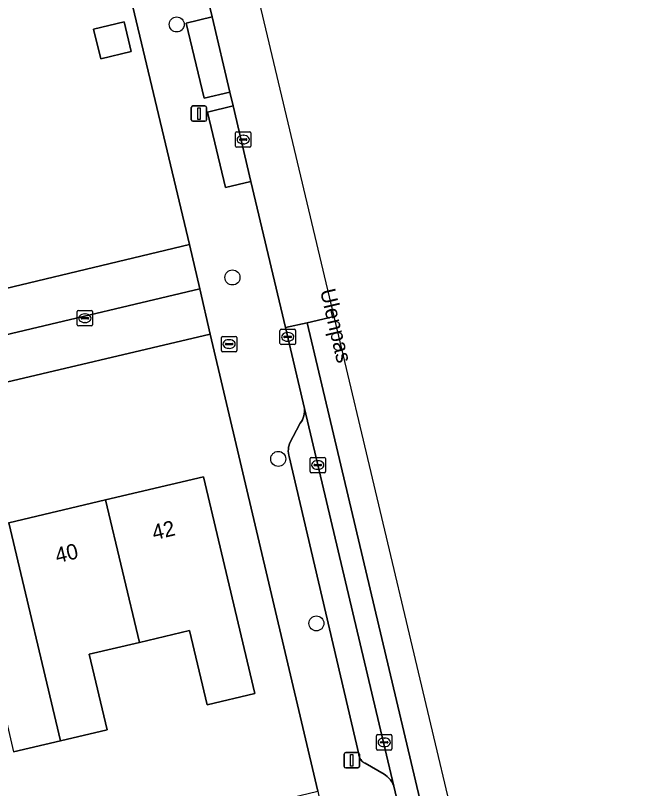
# Model space of a CAD drawing. Extents: x 157648 to 158502, y 379212 to 380938.
# Drawn here: x 158351.9 to 158392.5, y 380782.3 to 380832.6 of the extents above; entities that cross this region are included whole.
import ezdxf

# ---------------------------------------------------------------- set-up
doc = ezdxf.new("R2010")
doc.units = 0
for name, color, linetype in [('IMGEO_Boom', 7, 'Continuous'), ('IMGEO_Brandkraan', 7, 'Continuous'), ('IMGEO_Erf', 7, 'Continuous'), ('IMGEO_Groenvoorziening', 7, 'Continuous'), ('IMGEO_Kolk', 7, 'Continuous'), ('IMGEO_Lichtmast', 7, 'Continuous'), ('IMGEO_Openbare_ruimte_label', 7, 'Continuous'), ('IMGEO_Pand', 7, 'Continuous'), ('IMGEO_Pand_nummerreeks', 7, 'Continuous'), ('IMGEO_Parkeervlak_open', 7, 'Continuous'), ('IMGEO_Rijbaan_lokaal_gesloten', 7, 'Continuous'), ('IMGEO_Rijbaan_lokaal_open', 7, 'Continuous'), ('IMGEO_Voetpad_open', 7, 'Continuous')]:
    doc.layers.add(name, color=color, linetype=linetype)

msp = doc.modelspace()

# ---------------------------------------------------------------- linework, layer by layer
at = {"layer": 'IMGEO_Boom'}
for centre in [(158362.389, 380831.984), (158366.013, 380815.521), (158368.991, 380803.717), (158371.472, 380793.018)]:
    msp.add_circle(centre, 0.489, dxfattribs=at)
at = {"layer": 'IMGEO_Brandkraan'}
for p, q in [((158365.293, 380810.765), (158365.293, 380811.617)), ((158365.368, 380811.691), (158366.22, 380811.691)), ((158365.781, 380811.471), (158365.806, 380811.471)), ((158366.294, 380811.617), (158366.294, 380810.765)), ((158365.552, 380811.185), (158365.552, 380811.197)), ((158365.99, 380811.148), (158365.592, 380811.148)), ((158365.595, 380811.234), (158365.993, 380811.234)), ((158365.804, 380810.911), (158365.779, 380810.911)), ((158366.036, 380811.197), (158366.036, 380811.185)), ((158366.22, 380810.691), (158365.368, 380810.691))]:
    msp.add_line(p, q, dxfattribs=at)
for points in [[(158365.293, 380810.765), (158365.293, 380811.617)], [(158365.368, 380811.691), (158366.22, 380811.691)], [(158366.294, 380811.617), (158366.294, 380810.765)], [(158366.22, 380810.691), (158365.368, 380810.691)]]:
    msp.add_lwpolyline(points, dxfattribs=at)
for centre, radius, start, end in [((158365.37, 380811.615), 0.0765, 91.552, 178.448), ((158365.37, 380811.615), 0.0765, 91.552, 178.448), ((158366.218, 380811.615), 0.0765, 1.552, 88.448), ((158366.218, 380811.615), 0.0765, 1.552, 88.448), ((158365.37, 380810.767), 0.0765, 181.552, 268.448), ((158365.37, 380810.767), 0.0765, 181.552, 268.448), ((158365.592, 380811.194), 0.0403, 85.8775, 175.7526), ((158365.589, 380811.184), 0.0366, 178.938, 274.7102), ((158365.993, 380811.191), 0.043, 264.8664, 352.4533), ((158365.997, 380811.196), 0.0386, 1.7309, 96.639), ((158366.218, 380810.767), 0.0765, 271.552, 358.448), ((158366.218, 380810.767), 0.0765, 271.552, 358.448)]:
    msp.add_arc(centre, radius, start, end, dxfattribs=at)
for centre, major_axis, ratio, start_param, end_param in [((158365.78, 380811.191), (-0.387, 0.002), 0.722429, 4.712389, 7.853982), ((158365.805, 380811.191), (-0.39, 0.002), 0.717154, 1.570796, 4.712389)]:
    msp.add_ellipse(centre, major_axis=major_axis, ratio=ratio, start_param=start_param, end_param=end_param, dxfattribs=at)
at = {"layer": 'IMGEO_Erf'}
for points in [[(158346.135, 380837.142), (158347.662, 380830.717), (158348.081, 380828.951), (158350.047, 380829.418), (158351.124, 380824.885), (158349.158, 380824.417), (158350.661, 380818.095), (158345.233, 380816.805), (158344.065, 380816.528), (158343.54, 380816.403), (158344.245, 380813.436), (158344.77, 380813.561), (158345.938, 380813.838), (158346.006, 380813.552), (158363.215, 380817.667), (158352.177, 380864.073)], [(158344.495, 380775.601), (158371.565, 380782.109), (158364.564, 380811.841), (158335.11, 380804.894)], [(158351.466, 380799.554), (158357.767, 380801.046), (158364.124, 380802.552), (158367.46, 380788.461), (158364.364, 380787.728), (158363.221, 380792.554), (158359.96, 380791.782), (158356.699, 380791.01), (158357.865, 380786.089), (158354.825, 380785.369), (158351.786, 380784.65)]]:
    msp.add_lwpolyline(points, dxfattribs=at)
msp.add_lwpolyline([(158358.978, 380832.144), (158359.435, 380830.221), (158357.446, 380829.748), (158356.989, 380831.671)], close=True, dxfattribs=at)
at = {"layer": 'IMGEO_Groenvoorziening'}
msp.add_lwpolyline([(158363.902, 380814.78), (158363.215, 380817.667), (158346.006, 380813.552), (158338.72, 380811.781), (158339.383, 380808.977)], close=True, dxfattribs=at)
at = {"layer": 'IMGEO_Kolk'}
for p, q in [((158366.214, 380824.069), (158366.214, 380824.921)), ((158366.289, 380824.995), (158367.141, 380824.995)), ((158367.215, 380824.921), (158367.215, 380824.069)), ((158366.473, 380824.489), (158366.473, 380824.501)), ((158366.911, 380824.452), (158366.513, 380824.452)), ((158366.516, 380824.538), (158366.914, 380824.538)), ((158366.702, 380824.775), (158366.727, 380824.775)), ((158366.957, 380824.501), (158366.957, 380824.489)), ((158367.141, 380823.995), (158366.289, 380823.995)), ((158366.725, 380824.215), (158366.7, 380824.215)), ((158355.922, 380812.445), (158355.922, 380813.297)), ((158355.997, 380813.371), (158356.849, 380813.371)), ((158356.923, 380813.297), (158356.923, 380812.445)), ((158356.181, 380812.865), (158356.181, 380812.877)), ((158356.619, 380812.828), (158356.221, 380812.828)), ((158356.224, 380812.914), (158356.622, 380812.914)), ((158356.41, 380813.151), (158356.435, 380813.151)), ((158356.665, 380812.877), (158356.665, 380812.865)), ((158356.849, 380812.371), (158355.997, 380812.371)), ((158356.433, 380812.591), (158356.408, 380812.591)), ((158369.105, 380811.228), (158369.105, 380812.08)), ((158369.18, 380812.154), (158370.032, 380812.154)), ((158369.593, 380811.934), (158369.618, 380811.934)), ((158370.106, 380812.08), (158370.106, 380811.228)), ((158369.364, 380811.648), (158369.364, 380811.66)), ((158369.802, 380811.611), (158369.404, 380811.611)), ((158369.407, 380811.697), (158369.805, 380811.697)), ((158369.616, 380811.374), (158369.591, 380811.374)), ((158369.848, 380811.66), (158369.848, 380811.648)), ((158370.032, 380811.154), (158369.18, 380811.154)), ((158371.059, 380802.893), (158371.059, 380803.745)), ((158371.134, 380803.819), (158371.986, 380803.819)), ((158372.06, 380803.745), (158372.06, 380802.893)), ((158371.318, 380803.313), (158371.318, 380803.325)), ((158371.756, 380803.276), (158371.358, 380803.276)), ((158371.361, 380803.362), (158371.759, 380803.362)), ((158371.547, 380803.599), (158371.572, 380803.599)), ((158371.802, 380803.325), (158371.802, 380803.313)), ((158371.986, 380802.819), (158371.134, 380802.819)), ((158371.57, 380803.039), (158371.545, 380803.039)), ((158375.384, 380784.852), (158375.384, 380785.704)), ((158375.459, 380785.778), (158376.311, 380785.778)), ((158376.385, 380785.704), (158376.385, 380784.852)), ((158375.643, 380785.272), (158375.643, 380785.284)), ((158376.081, 380785.235), (158375.683, 380785.235)), ((158375.686, 380785.321), (158376.084, 380785.321)), ((158375.872, 380785.558), (158375.897, 380785.558)), ((158376.127, 380785.284), (158376.127, 380785.272)), ((158376.311, 380784.778), (158375.459, 380784.778)), ((158375.895, 380784.998), (158375.87, 380784.998))]:
    msp.add_line(p, q, dxfattribs=at)
for points in [[(158366.214, 380824.069), (158366.214, 380824.921)], [(158366.289, 380824.995), (158367.141, 380824.995)], [(158367.215, 380824.921), (158367.215, 380824.069)], [(158367.141, 380823.995), (158366.289, 380823.995)], [(158355.922, 380812.445), (158355.922, 380813.297)], [(158355.997, 380813.371), (158356.849, 380813.371)], [(158356.923, 380813.297), (158356.923, 380812.445)], [(158356.849, 380812.371), (158355.997, 380812.371)], [(158369.105, 380811.228), (158369.105, 380812.08)], [(158369.18, 380812.154), (158370.032, 380812.154)], [(158370.106, 380812.08), (158370.106, 380811.228)], [(158370.032, 380811.154), (158369.18, 380811.154)], [(158371.059, 380802.893), (158371.059, 380803.745)], [(158371.134, 380803.819), (158371.986, 380803.819)], [(158372.06, 380803.745), (158372.06, 380802.893)], [(158371.986, 380802.819), (158371.134, 380802.819)], [(158375.384, 380784.852), (158375.384, 380785.704)], [(158375.459, 380785.778), (158376.311, 380785.778)], [(158376.385, 380785.704), (158376.385, 380784.852)], [(158376.311, 380784.778), (158375.459, 380784.778)]]:
    msp.add_lwpolyline(points, dxfattribs=at)
for centre, radius, start, end in [((158366.291, 380824.919), 0.0765, 91.552, 178.448), ((158366.291, 380824.919), 0.0765, 91.552, 178.448), ((158367.139, 380824.919), 0.0765, 1.552, 88.448), ((158367.139, 380824.919), 0.0765, 1.552, 88.448), ((158366.513, 380824.498), 0.0403, 85.8775, 175.7526), ((158366.51, 380824.488), 0.0366, 178.938, 274.7102), ((158366.914, 380824.495), 0.043, 264.8664, 352.4533), ((158366.918, 380824.5), 0.0386, 1.7309, 96.639), ((158366.291, 380824.071), 0.0765, 181.552, 268.448), ((158366.291, 380824.071), 0.0765, 181.552, 268.448), ((158367.139, 380824.071), 0.0765, 271.552, 358.448), ((158367.139, 380824.071), 0.0765, 271.552, 358.448), ((158355.999, 380813.295), 0.0765, 91.552, 178.448), ((158355.999, 380813.295), 0.0765, 91.552, 178.448), ((158356.847, 380813.295), 0.0765, 1.552, 88.448), ((158356.847, 380813.295), 0.0765, 1.552, 88.448), ((158356.221, 380812.874), 0.0403, 85.8775, 175.7526), ((158356.218, 380812.864), 0.0366, 178.938, 274.7102), ((158356.622, 380812.871), 0.043, 264.8664, 352.4533), ((158356.626, 380812.876), 0.0386, 1.7309, 96.639), ((158355.999, 380812.447), 0.0765, 181.552, 268.448), ((158355.999, 380812.447), 0.0765, 181.552, 268.448), ((158356.847, 380812.447), 0.0765, 271.552, 358.448), ((158356.847, 380812.447), 0.0765, 271.552, 358.448), ((158369.182, 380812.078), 0.0765, 91.552, 178.448), ((158369.182, 380812.078), 0.0765, 91.552, 178.448), ((158370.03, 380812.078), 0.0765, 1.552, 88.448), ((158370.03, 380812.078), 0.0765, 1.552, 88.448), ((158369.404, 380811.657), 0.0403, 85.8775, 175.7526), ((158369.401, 380811.647), 0.0366, 178.938, 274.7102), ((158369.805, 380811.654), 0.043, 264.8664, 352.4533), ((158369.809, 380811.659), 0.0386, 1.7309, 96.639), ((158369.182, 380811.23), 0.0765, 181.552, 268.448), ((158369.182, 380811.23), 0.0765, 181.552, 268.448), ((158370.03, 380811.23), 0.0765, 271.552, 358.448), ((158370.03, 380811.23), 0.0765, 271.552, 358.448), ((158371.136, 380803.743), 0.0765, 91.552, 178.448), ((158371.136, 380803.743), 0.0765, 91.552, 178.448), ((158371.984, 380803.743), 0.0765, 1.552, 88.448), ((158371.984, 380803.743), 0.0765, 1.552, 88.448), ((158371.358, 380803.322), 0.0403, 85.8775, 175.7526), ((158371.355, 380803.312), 0.0366, 178.938, 274.7102), ((158371.759, 380803.319), 0.043, 264.8664, 352.4533), ((158371.763, 380803.324), 0.0386, 1.7309, 96.639), ((158371.136, 380802.895), 0.0765, 181.552, 268.448), ((158371.136, 380802.895), 0.0765, 181.552, 268.448), ((158371.984, 380802.895), 0.0765, 271.552, 358.448), ((158371.984, 380802.895), 0.0765, 271.552, 358.448), ((158375.461, 380785.702), 0.0765, 91.552, 178.448), ((158375.461, 380785.702), 0.0765, 91.552, 178.448), ((158376.309, 380785.702), 0.0765, 1.552, 88.448), ((158376.309, 380785.702), 0.0765, 1.552, 88.448), ((158375.683, 380785.281), 0.0403, 85.8775, 175.7526), ((158375.68, 380785.271), 0.0366, 178.938, 274.7102), ((158376.084, 380785.278), 0.043, 264.8664, 352.4533), ((158376.088, 380785.283), 0.0386, 1.7309, 96.639), ((158375.461, 380784.854), 0.0765, 181.552, 268.448), ((158375.461, 380784.854), 0.0765, 181.552, 268.448), ((158376.309, 380784.854), 0.0765, 271.552, 358.448), ((158376.309, 380784.854), 0.0765, 271.552, 358.448)]:
    msp.add_arc(centre, radius, start, end, dxfattribs=at)
for centre, major_axis, ratio, start_param, end_param in [((158366.701, 380824.495), (-0.387, 0.002), 0.722429, 4.712389, 7.853982), ((158366.726, 380824.495), (-0.39, 0.002), 0.717154, 1.570796, 4.712389), ((158356.409, 380812.871), (-0.387, 0.002), 0.722429, 4.712389, 7.853982), ((158356.434, 380812.871), (-0.39, 0.002), 0.717154, 1.570796, 4.712389), ((158369.592, 380811.654), (-0.387, 0.002), 0.722429, 4.712389, 7.853982), ((158369.617, 380811.654), (-0.39, 0.002), 0.717154, 1.570796, 4.712389), ((158371.546, 380803.319), (-0.387, 0.002), 0.722429, 4.712389, 7.853982), ((158371.571, 380803.319), (-0.39, 0.002), 0.717154, 1.570796, 4.712389), ((158375.871, 380785.278), (-0.387, 0.002), 0.722429, 4.712389, 7.853982), ((158375.896, 380785.278), (-0.39, 0.002), 0.717154, 1.570796, 4.712389)]:
    msp.add_ellipse(centre, major_axis=major_axis, ratio=ratio, start_param=start_param, end_param=end_param, dxfattribs=at)
at = {"layer": 'IMGEO_Lichtmast'}
for p, q in [((158363.336, 380825.783), (158363.336, 380826.583)), ((158363.336, 380826.583), (158363.336, 380825.783)), ((158363.436, 380826.683), (158364.226, 380826.683)), ((158364.226, 380826.683), (158363.436, 380826.683)), ((158364.326, 380826.583), (158364.326, 380825.783)), ((158364.326, 380825.783), (158364.326, 380826.583)), ((158364.226, 380825.683), (158363.436, 380825.683)), ((158363.436, 380825.683), (158364.226, 380825.683)), ((158373.38, 380784.611), (158374.17, 380784.611)), ((158374.17, 380784.611), (158373.38, 380784.611)), ((158373.28, 380783.711), (158373.28, 380784.511)), ((158373.28, 380784.511), (158373.28, 380783.711)), ((158374.27, 380784.511), (158374.27, 380783.711)), ((158374.27, 380783.711), (158374.27, 380784.511)), ((158374.17, 380783.611), (158373.38, 380783.611)), ((158373.38, 380783.611), (158374.17, 380783.611))]:
    msp.add_line(p, q, dxfattribs=at)
for points in [[(158363.756, 380826.558), (158363.906, 380826.558), (158363.906, 380825.808), (158363.756, 380825.808), (158363.756, 380826.558)], [(158373.7, 380784.486), (158373.85, 380784.486), (158373.85, 380783.736), (158373.7, 380783.736), (158373.7, 380784.486)]]:
    msp.add_lwpolyline(points, dxfattribs=at)
for centre, start, end in [((158363.436, 380826.583), 90, 180), ((158363.436, 380826.583), 90, 180), ((158364.226, 380826.583), 0, 90), ((158364.226, 380826.583), 360, 90), ((158363.436, 380825.783), 180, 270), ((158363.436, 380825.783), 180, 270), ((158364.226, 380825.783), 270, 0), ((158364.226, 380825.783), 270, 0), ((158373.38, 380784.511), 90, 180), ((158373.38, 380784.511), 90, 180), ((158374.17, 380784.511), 0, 90), ((158374.17, 380784.511), 360, 90), ((158373.38, 380783.711), 180, 270), ((158373.38, 380783.711), 180, 270), ((158374.17, 380783.711), 270, 0), ((158374.17, 380783.711), 270, 0)]:
    msp.add_arc(centre, 0.1, start, end, dxfattribs=at)
at = {"layer": 'IMGEO_Pand'}
for points in [[(158359.435, 380830.221), (158358.978, 380832.144), (158356.989, 380831.671), (158357.446, 380829.748)], [(158357.767, 380801.046), (158359.96, 380791.782), (158363.221, 380792.554), (158364.364, 380787.728), (158367.46, 380788.461), (158364.124, 380802.552)], [(158357.767, 380801.046), (158351.466, 380799.554), (158354.825, 380785.369), (158357.865, 380786.089), (158356.699, 380791.01), (158359.96, 380791.782)], [(158345.168, 380798.063), (158347.37, 380788.764), (158350.629, 380789.535), (158351.786, 380784.65), (158354.825, 380785.369), (158351.466, 380799.554)]]:
    msp.add_lwpolyline(points, close=True, dxfattribs=at)
at = {"layer": 'IMGEO_Parkeervlak_open'}
for points in [[(158364.691, 380832.473), (158363.007, 380832.077), (158364.183, 380827.181), (158365.847, 380827.574)], [(158367.219, 380821.763), (158366.055, 380826.693), (158364.381, 380826.278), (158365.559, 380821.376)], [(158376.507, 380782.435), (158370.69, 380806.999), (158370.694, 380806.912), (158370.69, 380806.78), (158370.674, 380806.648), (158370.647, 380806.519), (158370.608, 380806.392), (158370.558, 380806.269), (158370.497, 380806.152), (158370.426, 380806.04), (158369.728, 380804.726), (158369.691, 380804.601), (158369.665, 380804.474), (158369.65, 380804.344), (158369.647, 380804.214), (158369.656, 380804.084), (158369.676, 380803.956), (158369.695, 380803.876), (158374.231, 380784.5), (158374.238, 380784.438), (158374.251, 380784.377), (158374.27, 380784.317), (158374.293, 380784.259), (158374.322, 380784.204), (158374.356, 380784.151), (158374.394, 380784.101), (158374.436, 380784.055), (158374.482, 380784.014), (158374.532, 380783.976), (158374.585, 380783.943), (158374.645, 380783.913), (158375.882, 380783.203), (158375.961, 380783.147), (158376.077, 380783.05), (158376.185, 380782.944), (158376.282, 380782.828), (158376.369, 380782.704), (158376.444, 380782.573)]]:
    msp.add_lwpolyline(points, close=True, dxfattribs=at)
at = {"layer": 'IMGEO_Rijbaan_lokaal_gesloten'}
for points in [[(158372.618, 380812.974), (158372.618, 380812.974), (158370.865, 380812.579), (158379.338, 380776.722)], [(158381.005, 380777.591), (158372.618, 380812.974)]]:
    msp.add_lwpolyline(points, dxfattribs=at)
msp.add_lwpolyline([(158392.483, 380720.813), (158380.048, 380773.723), (158379.338, 380776.722), (158370.865, 380812.579), (158369.462, 380812.262), (158370.69, 380806.999), (158376.507, 380782.435), (158376.683, 380781.692), (158377.548, 380778.041), (158378.958, 380772.087), (158379.023, 380771.812), (158384.193, 380750), (158391.081, 380720.484)], close=True, dxfattribs=at)
at = {"layer": 'IMGEO_Rijbaan_lokaal_open'}
msp.add_lwpolyline([(158366.942, 380836.924), (158365.174, 380836.518), (158363.81, 380836.205), (158364.691, 380832.473), (158365.847, 380827.574), (158366.055, 380826.693), (158367.219, 380821.763), (158369.462, 380812.262), (158370.865, 380812.579), (158372.618, 380812.974), (158372.618, 380812.974), (158366.942, 380836.924)], dxfattribs=at)
at = {"layer": 'IMGEO_Voetpad_open'}
for points in [[(158352.177, 380864.073), (158363.215, 380817.667), (158363.902, 380814.78), (158364.564, 380811.841), (158371.565, 380782.109), (158371.974, 380779.995), (158386.193, 380720.467)], [(158363.007, 380832.077), (158364.691, 380832.473), (158363.81, 380836.205)], [(158376.683, 380781.692), (158376.507, 380782.435), (158376.444, 380782.573), (158376.369, 380782.704), (158376.282, 380782.828), (158376.185, 380782.944), (158376.077, 380783.05), (158375.961, 380783.147), (158375.882, 380783.203), (158374.645, 380783.913), (158374.585, 380783.943), (158374.532, 380783.976), (158374.482, 380784.014), (158374.436, 380784.055), (158374.394, 380784.101), (158374.356, 380784.151), (158374.322, 380784.204), (158374.293, 380784.259), (158374.27, 380784.317), (158374.251, 380784.377), (158374.238, 380784.438), (158374.231, 380784.5), (158369.695, 380803.876), (158369.676, 380803.956), (158369.656, 380804.084), (158369.647, 380804.214), (158369.65, 380804.344), (158369.665, 380804.474), (158369.691, 380804.601), (158369.728, 380804.726), (158370.426, 380806.04), (158370.497, 380806.152), (158370.558, 380806.269), (158370.608, 380806.392), (158370.647, 380806.519), (158370.674, 380806.648), (158370.69, 380806.78), (158370.694, 380806.912), (158370.69, 380806.999), (158369.462, 380812.262), (158367.219, 380821.763), (158365.559, 380821.376), (158364.381, 380826.278), (158366.055, 380826.693), (158365.847, 380827.574), (158364.183, 380827.181), (158363.007, 380832.077)]]:
    msp.add_lwpolyline(points, dxfattribs=at)
msp.add_lwpolyline([(158322.972, 380841.959), (158321.058, 380841.488), (158323.379, 380831.566), (158329, 380808.131), (158314.304, 380804.661), (158313.745, 380806.99), (158278.284, 380798.647), (158278.739, 380796.726), (158289.939, 380799.382), (158298.77, 380801.471), (158306.285, 380803.232), (158306.826, 380800.924), (158308.853, 380801.397), (158318.481, 380803.643), (158334.498, 380807.379), (158335.11, 380804.894), (158364.564, 380811.841), (158363.902, 380814.78), (158339.383, 380808.977), (158338.72, 380811.781), (158337.257, 380811.425), (158330.575, 380809.862)], close=True, dxfattribs=at)

# ---------------------------------------------------------------- texts
at = {"layer": 'IMGEO_Openbare_ruimte_label'}
msp.add_text('Ulenpas', height=1, rotation=283.2996, dxfattribs=at).set_placement((158371.703, 380814.662))
at = {"layer": 'IMGEO_Pand_nummerreeks'}
for s, p in [('42', (158360.918, 380798.422)), ('40', (158354.616, 380796.929))]:
    msp.add_text(s, height=1, rotation=13.324, dxfattribs=at).set_placement(p)

doc.saveas('drawing.dxf')
